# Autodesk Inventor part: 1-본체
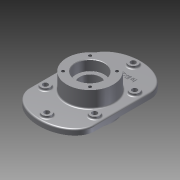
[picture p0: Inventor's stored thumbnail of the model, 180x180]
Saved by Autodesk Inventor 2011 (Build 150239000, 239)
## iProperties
Created: 2015-02
Part Number: 1-본체
Document SubType Name: Modeling
Designer: LINEART07
Density: 1 g/cm^3
Author: LINEART07
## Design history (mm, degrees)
sketch "스케치1"
  geometry: C1 r 50 at (0, 0); 1 further point
  constraints: 1 centre point, 1 coincident
extrude "돌출1" new body sketch "스케치1" distance "d0" = 23; taper "d1" = 0 deg
sketch "스케치2"
  geometry: L1 (0, 0)-(0, 60); L2 (0, 60)-(70, 60); L3 (70, 60)-(-70, 60); L4 (-70, 60)-(-70, -60); L5 (-70, -60)-(70, -60); L6 (70, -60)-(70, 60); L7 (0, 60)-(0, 110); C1 r 50 at (0, 0) reference
  constraints: 14 end point, 3 parallel, 2 perpendicular, 1 horizontal, 1 vertical
extrude "돌출2" join sketch "스케치2" distance "d2" = 12; taper "d3" = 0 deg
sketch "스케치3"
  geometry: C1 r 50 at (0, 0); 1 further point
  constraints: 1 centre point, 1 coincident
extrude "돌출3" join sketch "스케치3" distance "d4" = 35; taper "d5" = 0 deg
sketch "스케치4"
  geometry: C1 r 50 at (0, 0) reference; C2 r 31 at (0, 0)
  constraints: 1 centre point, 1 coincident
extrude "돌출4" cut sketch "스케치4" distance "d6" = 22; taper "d7" = 0 deg
sketch "스케치5"
  geometry: C1 r 50 at (0, 0) reference; C2 r 31 at (0, 0)
  constraints: 1 centre point, 1 coincident
extrude "돌출5" cut sketch "스케치5" distance "d8" = 22; taper "d9" = 0 deg
sketch "스케치6"
  geometry: C1 r 31 at (0, 0) reference; C2 r 22.5 at (0, 0)
  constraints: 1 centre point, 1 coincident
extrude "돌출6" cut sketch "스케치6" stored distance "d10" = 22; taper "d11" = 0 deg
sketch "스케치7"
  geometry: L1 (-70, 60)-(70, 60) reference; L2 (70, -60)-(-70, -60) reference; L3 (0, 60)-(0, 110); L4 (-70, -60)-(-53, -60); L5 (-53, -60)-(-53, 60); L6 (70, -60)-(53, -60); L7 (53, -60)-(53, 60); L8 (0, -60)-(0, -110); 2 further points; 2 other entities
  constraints: 14 end point, 4 point on line, 3 perpendicular, 2 coincident, 2 horizontal, 2 midpoint, 1 vertical, 8 other
extrude "돌출7" join sketch "스케치7" distance "d12" = 12; taper "d13" = 0 deg
sketch "스케치8"
  geometry: L1 (-70, -60)-(-70, 60) reference; L2 (-53, -60)-(-53, 60); L3 (53, 60)-(53, -60); C1 r 10 at (0, 93); C2 r 10 at (0, -93); C3 r 10 at (53, 43); C4 r 10 at (-53, 43); C5 r 10 at (-53, -43); C6 r 10 at (53, -43); 4 further points; 2 other entities
  constraints: 6 centre point, 4 end point, 1 parallel, 1 point on line, 10 other
extrude "돌출8" join sketch "스케치8" distance "d16" = 5; taper "d17" = 0 deg
sketch "스케치9"
  geometry: C1 r 10 at (0, 0) reference; C2 r 10 at (-106, 0) reference; C3 r 10 at (-53, -50) reference; C4 r 10 at (0, 86) reference; C5 r 10 at (-53, 136) reference; C6 r 10 at (-106, 86) reference; C7 r 5.5 at (0, 86); C8 r 5.5 at (0, 0); C9 r 5.5 at (-53, -50); C10 r 5.5 at (-106, 0); C11 r 5.5 at (-106, 86); C12 r 5.5 at (-53, 136); 1 further point
  constraints: 6 centre point, 6 coincident
extrude "돌출9" cut sketch "스케치9" stored distance "d18" = 5; taper "d19" = 0 deg
chamfer "모따기1" distance "d20" = 1; stored, may be unused: second distance "d21" = 2, angle "d22" = 45 deg
fillet "모깎기1" dims "d23" = 0.3
fillet "모깎기2" dims "d24" = 3
sketch "스케치10"
  geometry: L1 (0, 0)-(28.991, 28.991); L2 (-1.975, -1.975)-(-28.991, -28.991); L3 (0, 0)-(28.991, -28.991); L4 (0, 0)-(-28.991, 28.991); C1 r 32 at (0, 0) reference; A1 r 41 centre (0, 0) between (28.991, 28.991) and (-28.991, -28.991); 4 further points
  constraints: 8 end point, 5 coincident, 4 point on circle, 2 collinear, 1 centre point, 1 perpendicular
hole "Hole1" sketch "스케치10" at (-28.991, 28.991), (-28.991, -28.991), (28.991, -28.991), (28.991, 28.991) diameter "d25" = 6.401; stored, may be unused: countersink angle "d29" = 90 deg, drill point angle "d31" = 118 deg; dims "d26" = 10, "d27" = 4, "d28" = 2, "d30" = 13
sketch "스케치11"
  geometry: C1 r 3.2 at (-28.991, 28.991) reference; C2 r 3.2 at (28.991, 28.991) reference; C3 r 50 at (0, 0) reference; C4 r 32 at (0, 0) reference; C5 r 3.2 at (28.991, -28.991) reference; C6 r 3.2 at (-28.991, -28.991) reference; 4 further points
  constraints: 4 coincident
hole "Hole2" sketch "스케치11" at (-28.991, 28.991), (-28.991, -28.991), (28.991, -28.991), (28.991, 28.991) diameter "d32" = 6.401; stored, may be unused: countersink angle "d36" = 90 deg, drill point angle "d38" = 118 deg; dims "d33" = 10, "d34" = 4, "d35" = 2, "d37" = 13
sketch "스케치12"
  geometry: L1 (-67, -60)-(-67, 60) reference; L2 (0, 0)-(0, 65); L3 (-55.717, 71.822)-(56.671, 71.822); L4 (56.671, 71.822)-(56.671, 58.825); L5 (56.671, 58.825)-(-55.717, 58.825); L6 (-55.717, 58.825)-(-55.717, 71.822); C1 r 53 at (0, 0) reference
  constraints: 2 end point, 1 parallel, 2 other
extrude "돌출10" join sketch "스케치12" distance "d39" = 1; taper "d40" = 0 deg
node "솔리드1"
node "투영된 루프1"
node "투영된 루프2"
node "투영된 루프3"
node "투영된 루프4"
node "투영된 루프5"
node "투영된 루프6"
